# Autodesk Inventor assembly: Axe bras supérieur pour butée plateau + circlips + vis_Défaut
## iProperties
Shininess: 64.0
Length Units: 11269
Angle Units: 11279
Time Units: 11290
Mass Units: 11283
Length Display Precision: 3
Angle Display Precision: 2
Compacted: True
Created: 2006-11
Part Number: Axe bras supérieur pour butée plateau + circlips + vis_Défaut
Document SubType Name: Assembly
Designer: profs_sti
Density: 0.0
Volumn: 0.0
Area: 0.0
PropertySet Name: Model Information
Control State: 0
Master: False
Checked Out: False
Author: profs_sti
